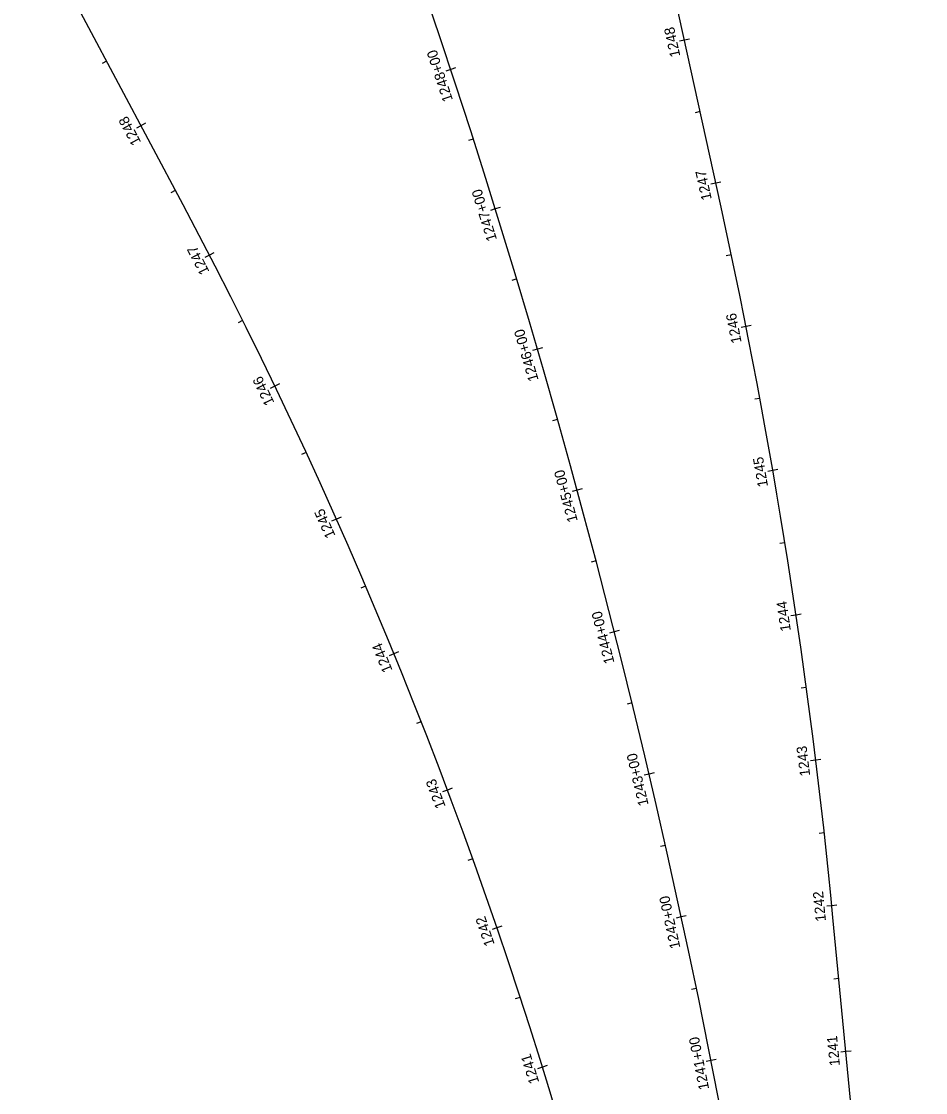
# Model space of a CAD drawing. Extents: x 596007 to 607538, y 326212 to 405053.
# Drawn here: x 603769 to 604386, y 348880 to 349611 of the extents above; entities that cross this region are included whole.
import ezdxf

# ---------------------------------------------------------------- set-up
doc = ezdxf.new("R2010")
doc.units = 0
for name, color, linetype in [('P_ALI', 7, 'Continuous'), ('P_ALI_200', 7, 'Continuous'), ('P_ALI_200_Sta', 7, 'Continuous')]:
    doc.layers.add(name, color=color, linetype=linetype)

msp = doc.modelspace()

# ---------------------------------------------------------------- linework, layer by layer
at = {"layer": 'P_ALI'}
for points in [[(604246.74, 349484.42), (604184.47, 349768.09)], [(603879.41, 349486.01), (603769.04, 349693.44)], [(604386.32, 348345.29), (604323.1, 348999.57)]]:
    msp.add_lwpolyline(points, dxfattribs=at)
for centre, radius, start, end in [((600886.71, 347893.57), 3390, 2.65733, 28.01789), ((600242.11, 348605.27), 4100, 5.51866, 12.38184)]:
    msp.add_arc(centre, radius, start, end, dxfattribs=at)
at = {"layer": 'P_ALI_200'}
msp.add_arc((598624.15, 347788.56), 5725, 359.01831, 20.85479, dxfattribs=at)
at = {"layer": 'P_ALI_200_Sta'}
for points in [[(604221.68, 349598.56), (604218.26, 349597.81)], [(604225.1, 349599.31), (604221.68, 349598.56)], [(604221.68, 349598.56), (604221.68, 349598.56)], [(603827.14, 349584.25), (603824.05, 349582.6)], [(604062.13, 349578.55), (604058.8, 349577.45)], [(604065.45, 349579.64), (604062.13, 349578.55)], [(604062.13, 349578.55), (604062.13, 349578.55)], [(604232.4, 349549.72), (604228.99, 349548.97)], [(603850.63, 349540.11), (603847.54, 349538.46)], [(603853.72, 349541.75), (603850.63, 349540.11)], [(603850.63, 349540.11), (603850.63, 349540.11)], [(604077.55, 349530.99), (604074.22, 349529.92)], [(603874.11, 349495.97), (603871.02, 349494.32)], [(604243.13, 349500.89), (604239.71, 349500.14)], [(604246.54, 349501.64), (604243.13, 349500.89)], [(604243.13, 349500.89), (604243.13, 349500.89)], [(604092.56, 349483.29), (604089.22, 349482.26)], [(604095.9, 349484.33), (604092.56, 349483.29)], [(604092.56, 349483.29), (604092.56, 349483.29)], [(603897.4, 349451.73), (603894.3, 349450.12)], [(603900.51, 349453.33), (603897.4, 349451.73)], [(603897.4, 349451.73), (603897.4, 349451.73)], [(604253.72, 349452.02), (604250.29, 349451.3)], [(604107.15, 349435.47), (604103.8, 349434.46)], [(603920.06, 349407.15), (603916.93, 349405.59)], [(604263.74, 349403.04), (604260.31, 349402.36)], [(604267.18, 349403.72), (604263.74, 349403.04)], [(604263.74, 349403.04), (604263.74, 349403.04)], [(604121.33, 349387.52), (604117.97, 349386.54)], [(604124.69, 349388.5), (604121.33, 349387.52)], [(604121.33, 349387.52), (604121.33, 349387.52)], [(603942.05, 349362.25), (603938.9, 349360.73)], [(603945.21, 349363.77), (603942.05, 349362.25)], [(603942.05, 349362.25), (603942.05, 349362.25)], [(604273.17, 349353.94), (604269.73, 349353.3)], [(604135.08, 349339.45), (604131.71, 349338.5)], [(603963.38, 349317.03), (603960.2, 349315.56)], [(604282, 349304.72), (604278.55, 349304.13)], [(604285.45, 349305.32), (604282, 349304.72)], [(604282, 349304.72), (604282, 349304.72)], [(604148.42, 349291.26), (604145.04, 349290.34)], [(604151.79, 349292.18), (604148.42, 349291.26)], [(604148.42, 349291.26), (604148.42, 349291.26)], [(603984.04, 349271.5), (603980.84, 349270.07)], [(603987.24, 349272.92), (603984.04, 349271.5)], [(603984.04, 349271.5), (603984.04, 349271.5)], [(604290.23, 349255.4), (604286.78, 349254.85)], [(604161.33, 349242.96), (604157.94, 349242.07)], [(604004.03, 349225.66), (604000.81, 349224.29)], [(604297.86, 349205.99), (604294.4, 349205.48)], [(604301.32, 349206.5), (604297.86, 349205.99)], [(604297.86, 349205.99), (604297.86, 349205.99)], [(604173.82, 349194.54), (604170.43, 349193.68)], [(604177.21, 349195.4), (604173.82, 349194.54)], [(604173.82, 349194.54), (604173.82, 349194.54)], [(604023.33, 349179.54), (604020.09, 349178.22)], [(604026.57, 349180.87), (604023.33, 349179.54)], [(604023.33, 349179.54), (604023.33, 349179.54)], [(604304.88, 349156.49), (604301.42, 349156.02)], [(604185.89, 349146.02), (604182.49, 349145.19)], [(604041.96, 349133.14), (604038.7, 349131.86)], [(604311.3, 349106.9), (604307.83, 349106.47)], [(604314.78, 349107.33), (604311.3, 349106.9)], [(604311.3, 349106.9), (604311.3, 349106.9)], [(604197.53, 349097.39), (604194.12, 349096.59)], [(604200.94, 349098.19), (604197.53, 349097.39)], [(604197.53, 349097.39), (604197.53, 349097.39)], [(604059.9, 349086.47), (604056.62, 349085.24)], [(604063.17, 349087.7), (604059.9, 349086.47)], [(604059.9, 349086.47), (604059.9, 349086.47)], [(604317.12, 349057.24), (604313.64, 349056.85)], [(604208.75, 349048.67), (604205.33, 349047.9)], [(604077.15, 349039.54), (604073.85, 349038.36)], [(604322.33, 349007.51), (604318.84, 349007.17)], [(604325.81, 349007.86), (604322.33, 349007.51)], [(604322.33, 349007.51), (604322.33, 349007.51)], [(604219.54, 348999.85), (604216.12, 348999.11)], [(604222.96, 349000.59), (604219.54, 348999.85)], [(604219.54, 348999.85), (604219.54, 348999.85)], [(604093.7, 348992.36), (604090.39, 348991.23)], [(604097.01, 348993.5), (604093.7, 348992.36)], [(604093.7, 348992.36), (604093.7, 348992.36)], [(604327.14, 348957.74), (604323.66, 348957.41)], [(604229.91, 348950.93), (604226.48, 348950.22)], [(604109.56, 348944.94), (604106.23, 348943.86)], [(604331.95, 348907.98), (604328.47, 348907.64)], [(604335.44, 348908.31), (604331.95, 348907.98)], [(604331.95, 348907.98), (604331.95, 348907.98)], [(604124.71, 348897.3), (604121.37, 348896.26)], [(604128.06, 348898.33), (604124.71, 348897.3)], [(604124.71, 348897.3), (604124.71, 348897.3)], [(604239.84, 348901.93), (604236.41, 348901.25)], [(604243.28, 348902.61), (604239.84, 348901.93)], [(604239.84, 348901.93), (604239.84, 348901.93)]]:
    msp.add_lwpolyline(points, dxfattribs=at)

# ---------------------------------------------------------------- texts
for s, rotation, p in [('1248', 102.38184, (604218.95, 349587.7)), ('1248+00', 108.21968, (604063.72, 349557.71)), ('1248', 118.01789, (603850.92, 349528.91)), ('1247', 102.38184, (604240.39, 349490.02)), ('1247+00', 107.21888, (604093.79, 349462.43)), ('1247', 117.36339, (603897.57, 349440.52)), ('1246', 101.21998, (604260.79, 349392.23)), ('1246+00', 106.21808, (604122.19, 349366.64)), ('1246', 115.67325, (603941.89, 349351.05)), ('1245', 99.82253, (604278.79, 349293.99)), ('1245+00', 105.21728, (604148.92, 349270.37)), ('1245', 113.98311, (603983.55, 349260.3)), ('1244', 98.42507, (604294.38, 349195.34)), ('1244+00', 104.21648, (604173.96, 349173.64)), ('1244', 112.29297, (604022.51, 349168.37)), ('1243', 97.02761, (604307.57, 349096.34)), ('1243+00', 103.21568, (604197.3, 349076.5)), ('1243', 110.60283, (604058.75, 349075.33)), ('1242+00', 102.21488, (604218.95, 348978.96)), ('1242', 95.63015, (604318.33, 348997.04)), ('1242', 108.91269, (604092.22, 348981.26)), ('1241', 95.51866, (604327.85, 348898.41)), ('1241+00', 101.21409, (604238.6, 348882.5)), ('1241', 107.22255, (604122.64, 348887.1))]:
    msp.add_text(s, height=7, rotation=rotation, dxfattribs=at).set_placement(p)

doc.saveas('drawing.dxf')
